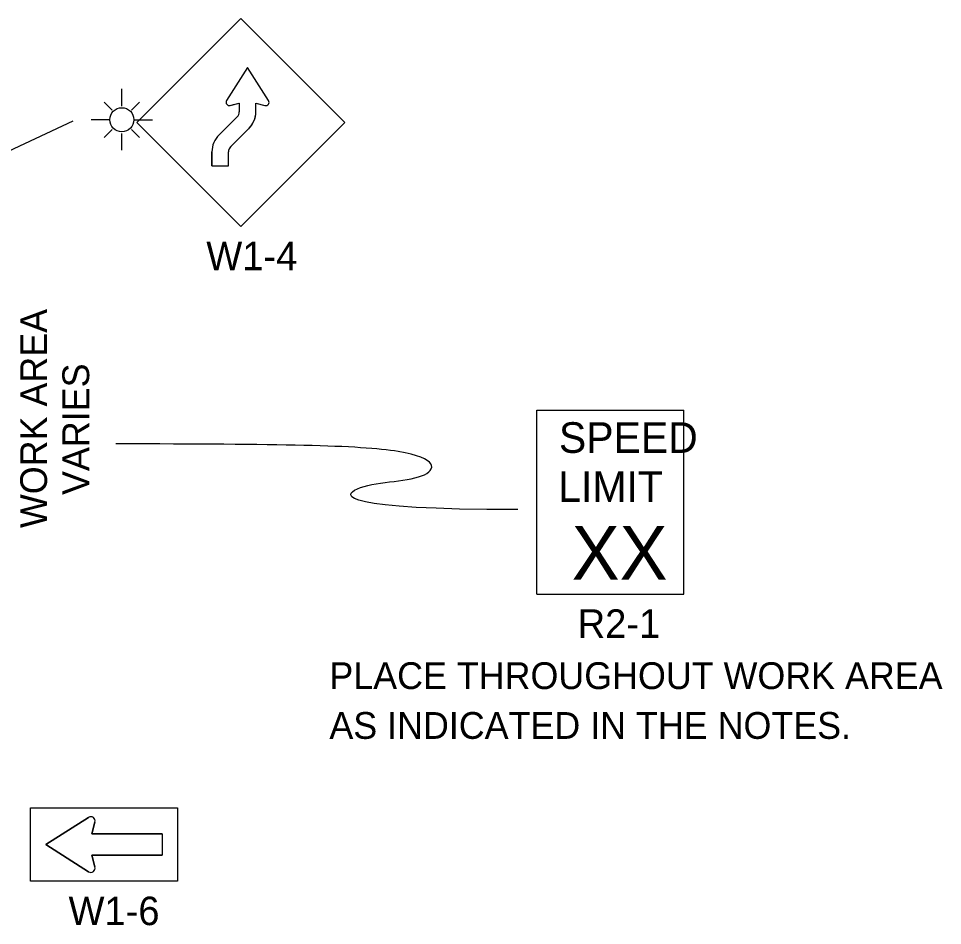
# Model space of a CAD drawing. Extents: x 16738 to 19504, y 5697 to 6916.
# Drawn here: x 17164.6 to 17406, y 6296.1 to 6532.9 of the extents above; entities that cross this region are included whole.
import ezdxf

# ---------------------------------------------------------------- set-up
doc = ezdxf.new("R2010")
doc.units = 0
doc.layers.add('TRAFFIC_SIGNS_PR', color=7, linetype='Continuous')
doc.layers.add('TYPICAL_TEXT_DIMEN_PR', color=7, linetype='Continuous')

msp = doc.modelspace()

# ---------------------------------------------------------------- linework, layer by layer
at = {"layer": 'TRAFFIC_SIGNS_PR'}
for p, q in [((17222.66, 6532.95), (17195.5, 6505.8)), ((17249.81, 6505.8), (17222.66, 6532.95)), ((17191.59, 6510.07), (17191.59, 6514.57)), ((17189.08, 6509.03), (17186.97, 6511.13)), ((17194.11, 6509.03), (17196.21, 6511.13)), ((17188.44, 6506.51), (17183.6, 6506.51)), ((17194.75, 6506.51), (17199.63, 6506.51)), ((17195.5, 6505.8), (17222.66, 6478.64)), ((17217, 6502.55), (17221.72, 6507.26)), ((17221.72, 6507.26), (17217, 6502.55)), ((17222.66, 6478.64), (17249.81, 6505.8)), ((17189.08, 6504), (17186.97, 6501.89)), ((17191.59, 6498.55), (17191.59, 6502.96)), ((17194.11, 6504), (17196.21, 6501.89)), ((17220.05, 6499.49), (17224.77, 6504.21)), ((17220.05, 6499.49), (17224.77, 6504.21)), ((17215.13, 6494.43), (17215.13, 6498.12)), ((17219.45, 6494.43), (17219.45, 6498.12)), ((17215.13, 6494.43), (17219.45, 6494.43)), ((17300, 6430.66), (17338.4, 6430.66)), ((17300, 6382.66), (17300, 6430.66)), ((17338.4, 6382.66), (17338.4, 6430.66)), ((17300, 6382.66), (17338.4, 6382.66)), ((17182.89, 6324.34), (17171.73, 6317.24)), ((17183.73, 6320.04), (17184.57, 6323.1)), ((17202.13, 6320.04), (17183.73, 6320.04)), ((17202.13, 6320.04), (17202.13, 6314.44)), ((17171.73, 6317.24), (17182.89, 6310.14)), ((17184.57, 6311.38), (17183.73, 6314.44)), ((17183.73, 6314.44), (17202.13, 6314.44))]:
    msp.add_line(p, q, dxfattribs=at)
for points in [[(17229.92, 6511.54), (17224.44, 6520.14), (17218.96, 6511.53)], [(17229.92, 6511.53), (17224.44, 6520.14), (17218.96, 6511.53)], [(17219.92, 6510.24), (17222.28, 6510.88), (17222.28, 6508.59)], [(17219.92, 6510.24), (17220.75, 6510.46), (17222.28, 6510.88), (17222.28, 6508.59)], [(17226.59, 6508.52), (17226.6, 6510.88), (17228.96, 6510.24)], [(17215.13, 6498.12), (17215.13, 6494.43), (17219.45, 6494.43), (17219.45, 6498.12)], [(17182.89, 6310.14), (17171.73, 6317.24), (17182.89, 6324.34)], [(17184.57, 6323.1), (17183.73, 6320.04), (17202.13, 6320.04), (17202.13, 6314.44), (17183.73, 6314.44), (17184.57, 6311.38)]]:
    msp.add_lwpolyline(points, dxfattribs=at)
msp.add_lwpolyline([(17206.13, 6307.64), (17167.73, 6307.64), (17167.73, 6326.84), (17206.13, 6326.84)], close=True, dxfattribs=at)
msp.add_circle((17191.59, 6506.51), 3.15, dxfattribs=at)
for centre, radius, start, end in [((17219.69, 6511.07), 0.864, 147.5204, 285.3986), ((17219.69, 6511.07), 0.866, 147.5288, 285.3852), ((17229.19, 6511.07), 0.866, 254.6799, 32.2804), ((17220.43, 6508.59), 1.85, 314.2125, 0), ((17220.43, 6508.59), 1.85, 314.2123, 0.1238), ((17220.43, 6508.59), 6.17, 314.2125, 359.3819), ((17220.43, 6508.59), 6.17, 314.7687, 359.3755), ((17221.3, 6498.13), 6.17, 134.2125, 180), ((17221.3, 6498.13), 6.17, 134.2125, 180), ((17221.3, 6498.13), 6.17, 134.2117, 180), ((17221.3, 6498.13), 1.85, 132.372, 180), ((17221.3, 6498.13), 1.85, 134.2125, 180), ((17183.49, 6323.4), 1.12, 344.6731, 122.4696), ((17183.49, 6323.4), 1.12, 344.6731, 122.4696), ((17183.49, 6311.09), 1.12, 237.5304, 15.3269), ((17183.49, 6311.09), 1.12, 237.5304, 15.3269)]:
    msp.add_arc(centre, radius, start, end, dxfattribs=at)
at = {"layer": 'TYPICAL_TEXT_DIMEN_PR'}
msp.add_line((17178.79, 6506.12), (17152.76, 6494.01), dxfattribs=at)
msp.add_open_spline([(17295.02, 6404.69), (17248.93, 6404.69), (17248.93, 6411.96), (17274.11, 6411.96), (17274.11, 6421.28), (17232.93, 6421.81), (17190.03, 6421.86)], degree=3, dxfattribs=at)

# ---------------------------------------------------------------- texts
at = {"layer": 'TRAFFIC_SIGNS_PR'}
for s, height, p in [('W1-4', 7.44, (17213.66, 6467.21)), ('SPEED', 8, (17305.77, 6419.52)), ('LIMIT', 8, (17305.6, 6406.72)), ('XX', 14.031, (17309.11, 6386.41)), ('R2-1', 7.44, (17310.67, 6371.22)), ('PLACE THROUGHOUT WORK AREA', 7, (17245.81, 6357.84)), ('AS INDICATED IN THE NOTES.', 7, (17245.81, 6344.84)), ('W1-6', 7.44, (17177.67, 6296.2))]:
    msp.add_text(s, height=height, dxfattribs=at).set_placement(p)
at = {"layer": 'TYPICAL_TEXT_DIMEN_PR'}
for s, p in [('WORK AREA', (17172.06, 6399.89)), ('VARIES', (17183.06, 6408.53))]:
    msp.add_text(s, height=7, rotation=90, dxfattribs=at).set_placement(p)

doc.saveas('drawing.dxf')
